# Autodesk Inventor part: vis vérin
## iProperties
Shininess: 20.0
Angle Display Precision: 2
Document Length Units: 11269
Document Angle Units: 11279
Document Time Units: 11290
Document Mass Units: 11283
Document Length Units Precision: 3
Document Angle Units Precision: 2
Created: 2002-09
Part Number: vis vérin
Material: Par défaut
Document SubType Name: Modélisation
Designer: administrateur
Density: 0.0
Volumn: 0.0
Area: 0.0
PropertySet Name: Model Information
Control State: 0
Master: False
Checked Out: False
Author: administrateur
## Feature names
1. Extrusion1
